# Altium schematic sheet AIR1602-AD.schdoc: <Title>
size 419 x 266 mm; Name: SIZEB; Symbol: SIZEB; Device: SIZEB; Drawn By: <Drawn By>; Checked By: <Checked By>; QC By: <QC By>; Released By: <Released By>; Drawn Date: <Drawn Date>; Checked Date: <Checked Date>; QC Date: <QC Date>; Release Date: <Release Date>; Company Name: <Company Name>; Code: <Code>; Sheet Size: B; Drawing Number: <Drawing Number>; Revision: <Revision>; Scale: <Scale>; Sheet Number: 1; Number of Sheets: 1
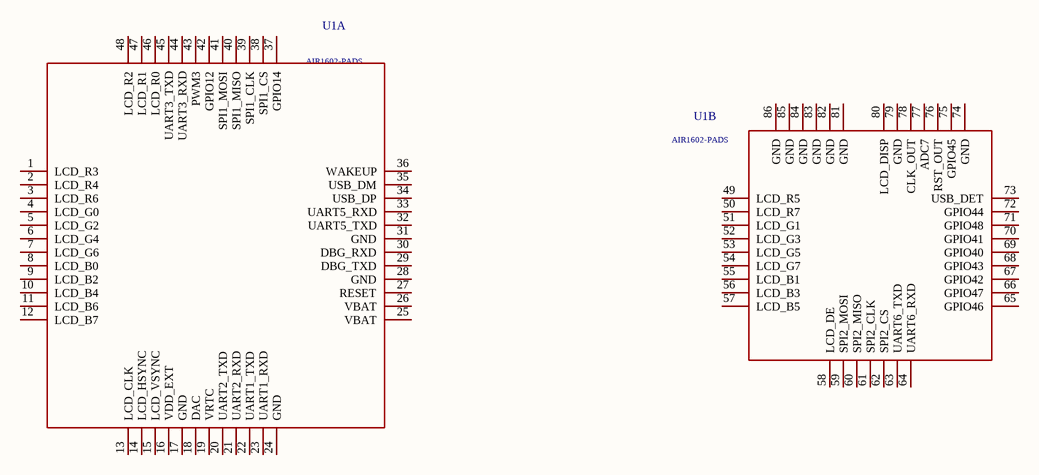
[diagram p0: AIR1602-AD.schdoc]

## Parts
U1  AIR1602-PADS  (parts A,B of 2)

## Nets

Not connected (* = marked no-connect by the designer): U1 1(LCD_R3) 2(LCD_R4) 3(LCD_R6) 4(LCD_G0) 5(LCD_G2) 6(LCD_G4) 7(LCD_G6) 8(LCD_B0) 9(LCD_B2) 10(LCD_B4) 11(LCD_B6) 12(LCD_B7) 13(LCD_CLK) 14(LCD_HSYNC) 15(LCD_VSYNC) 16(VDD_EXT) 17(GND) 18(DAC) 19(VRTC) 20(UART2_TXD) 21(UART2_RXD) 22(UART1_TXD) 23(UART1_RXD) 24(GND) 25(VBAT) 26(VBAT) 27(RESET) 28(GND) 29(DBG_TXD) 30(DBG_RXD) 31(GND) 32(UART5_TXD) 33(UART5_RXD) 34(USB_DP) 35(USB_DM) 36(WAKEUP) 37(GPIO14) 38(SPI1_CS) 39(SPI1_CLK) 40(SPI1_MISO) 41(SPI1_MOSI) 42(GPIO12) 43(PWM3) 44(UART3_RXD) 45(UART3_TXD) 46(LCD_R0) 47(LCD_R1) 48(LCD_R2) 49(LCD_R5) 50(LCD_R7) 51(LCD_G1) 52(LCD_G3) 53(LCD_G5) 54(LCD_G7) 55(LCD_B1) 56(LCD_B3) 57(LCD_B5) 58(LCD_DE) 59(SPI2_MOSI) 60(SPI2_MISO) 61(SPI2_CLK) 62(SPI2_CS) 63(UART6_TXD) 64(UART6_RXD) 65(GPIO46) 66(GPIO47) 67(GPIO42) 68(GPIO43) 69(GPIO40) 70(GPIO41) 71(GPIO48) 72(GPIO44) 73(USB_DET) 74(GND) 75(GPIO45) 76(RST_OUT) 77(ADC7) 78(CLK_OUT) 79(GND) 80(LCD_DISP) 81(GND) 82(GND) 83(GND) 84(GND) 85(GND) 86(GND)

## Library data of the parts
U1 = AIR1602-PADS: Add into BOM: yes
